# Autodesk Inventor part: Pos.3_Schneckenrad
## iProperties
Created: 2008-10
Part Number: Pos.3_Schneckenrad
Document SubType Name: Modeling
Designer: nkrapf
Density: 1 g/cm^3
Author: nkrapf
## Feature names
1. Umdrehung1 [Revolution]
2. Bohrung1 [Hole]
